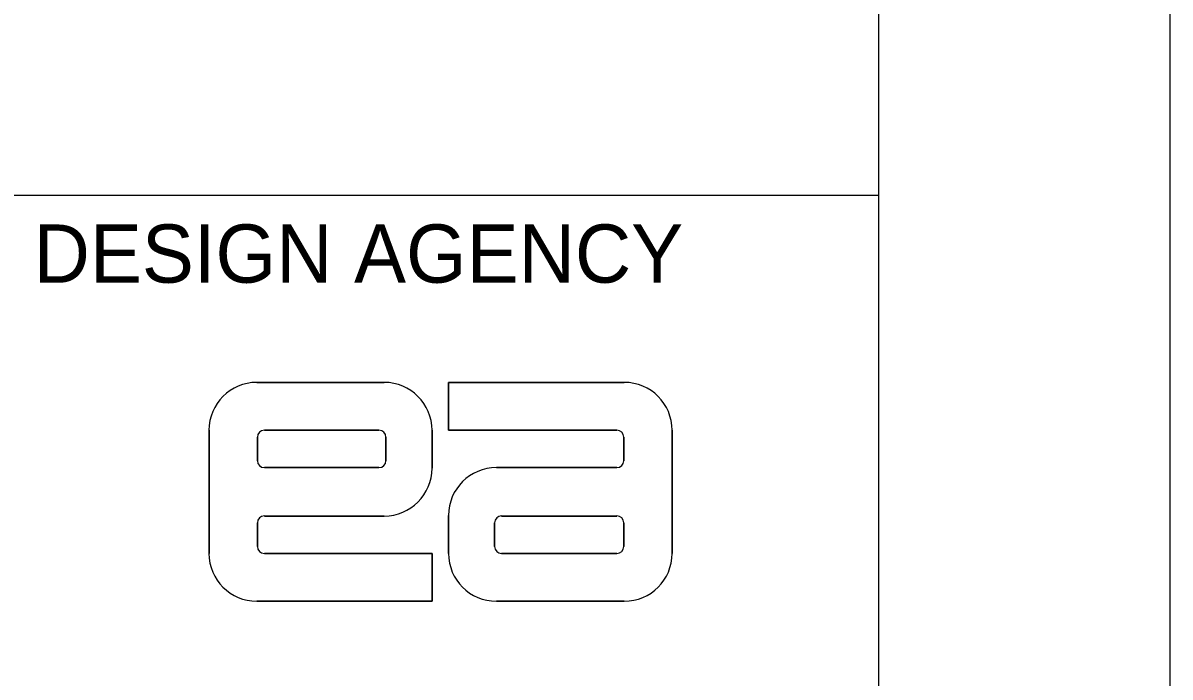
# Model space of a CAD drawing. Extents: x 0 to 34, y 0 to 22.
# Drawn here: x 32.032 to 34, y 3.673 to 4.796 of the extents above; entities that cross this region are included whole.
import ezdxf

# ---------------------------------------------------------------- set-up
doc = ezdxf.new("R2010")
doc.units = 0
for name, color, linetype in [('SH_Border', 7, 'Continuous'), ('SH_Cut_Line', 7, 'Continuous'), ('SH_Data', 7, 'Continuous'), ('TX_X_20', 7, 'Continuous')]:
    doc.layers.add(name, color=color, linetype=linetype)

msp = doc.modelspace()

# ---------------------------------------------------------------- linework, layer by layer
at = {"layer": 'SH_Border'}
msp.add_line((32, 4.5), (33.5, 4.5), dxfattribs=at)
msp.add_lwpolyline([(1.5, 21.5), (33.5, 21.5), (33.5, 0.5), (1.5, 0.5)], close=True, dxfattribs=at)
at = {"layer": 'SH_Cut_Line'}
msp.add_lwpolyline([(0, 0), (34, 0), (34, 22), (0, 22)], close=True, dxfattribs=at)
at = {"layer": 'TX_X_20'}
for p, q in [((32.6515, 4.1788), (32.433, 4.1788)), ((32.433, 4.1788), (32.6515, 4.1788)), ((32.762, 4.1788), (33.0635, 4.1788)), ((32.762, 4.0967), (32.762, 4.1788)), ((32.351, 4.0967), (32.351, 3.8852)), ((32.351, 3.8852), (32.351, 4.0967)), ((32.4459, 4.0967), (32.6426, 4.0967)), ((32.6426, 4.0967), (32.4459, 4.0967)), ((32.7336, 4.0315), (32.7336, 4.0967)), ((32.7336, 4.0967), (32.7336, 4.0315)), ((33.0507, 4.0967), (32.762, 4.0967)), ((33.1456, 3.8852), (33.1456, 4.0967)), ((33.1456, 4.0967), (33.1456, 3.8852)), ((32.434, 4.0444), (32.434, 4.0849)), ((32.434, 4.0849), (32.434, 4.0444)), ((32.6545, 4.0849), (32.6545, 4.0444)), ((32.6545, 4.0444), (32.6545, 4.0849)), ((33.0626, 4.0849), (33.0626, 4.0444)), ((33.0626, 4.0444), (33.0626, 4.0849)), ((32.6426, 4.0325), (32.4459, 4.0325)), ((32.4459, 4.0325), (32.6426, 4.0325)), ((33.0507, 4.0325), (32.8441, 4.0325)), ((32.8441, 4.0325), (33.0507, 4.0325)), ((32.434, 3.8971), (32.434, 3.9376)), ((32.434, 3.9376), (32.434, 3.8971)), ((32.4459, 3.9494), (32.6515, 3.9494)), ((32.6515, 3.9494), (32.4459, 3.9494)), ((32.762, 3.9504), (32.762, 3.8852)), ((32.762, 3.8852), (32.762, 3.9504)), ((32.8411, 3.8971), (32.8411, 3.9376)), ((32.8411, 3.9376), (32.8411, 3.8971)), ((32.853, 3.9494), (33.0507, 3.9494)), ((33.0507, 3.9494), (32.853, 3.9494)), ((33.0626, 3.9376), (33.0626, 3.8971)), ((33.0626, 3.8971), (33.0626, 3.9376)), ((32.4459, 3.8852), (32.7336, 3.8852)), ((32.7336, 3.8852), (32.7336, 3.8031)), ((33.0507, 3.8852), (32.853, 3.8852)), ((32.853, 3.8852), (33.0507, 3.8852)), ((32.7336, 3.8031), (32.433, 3.8031)), ((32.8441, 3.8031), (33.0635, 3.8031)), ((33.0635, 3.8031), (32.8441, 3.8031))]:
    msp.add_line(p, q, dxfattribs=at)
for points in [[(33.0635, 4.1788), (32.762, 4.1788), (32.762, 4.0967), (33.0507, 4.0967)], [(32.433, 3.8031), (32.7336, 3.8031), (32.7336, 3.8852), (32.4459, 3.8852)]]:
    msp.add_lwpolyline(points, dxfattribs=at)
for centre, radius, start, end in [((32.433, 4.0967), 0.0821, 90, 180), ((32.433, 4.0967), 0.0821, 90, 180), ((32.6515, 4.0967), 0.0821, 0, 90), ((32.6515, 4.0967), 0.0821, 0, 90), ((33.0635, 4.0967), 0.0821, 0, 90), ((33.0635, 4.0967), 0.0821, 0, 90), ((32.4459, 4.0849), 0.0119, 90, 180), ((32.4459, 4.0849), 0.0119, 90, 180), ((32.6426, 4.0849), 0.0119, 0, 90), ((32.6426, 4.0849), 0.0119, 0, 90), ((33.0507, 4.0849), 0.0119, 0, 90), ((33.0507, 4.0849), 0.0119, 0, 90), ((32.4459, 4.0444), 0.0119, 180, 270), ((32.4459, 4.0444), 0.0119, 180, 270), ((32.6426, 4.0444), 0.0119, 270, 0), ((32.6426, 4.0444), 0.0119, 270, 0), ((33.0507, 4.0444), 0.0119, 270, 0), ((33.0507, 4.0444), 0.0119, 270, 0), ((32.6515, 4.0315), 0.0821, 270, 360), ((32.6515, 4.0315), 0.0821, 270, 360), ((32.8441, 3.9504), 0.0821, 90, 180), ((32.8441, 3.9504), 0.0821, 90, 180), ((32.4459, 3.9376), 0.0119, 90, 180), ((32.4459, 3.9376), 0.0119, 90, 180), ((32.853, 3.9376), 0.0119, 90, 180), ((32.853, 3.9376), 0.0119, 90, 180), ((33.0507, 3.9376), 0.0119, 0, 90), ((33.0507, 3.9376), 0.0119, 0, 90), ((32.433, 3.8852), 0.0821, 180, 270), ((32.433, 3.8852), 0.0821, 180, 270), ((32.4459, 3.8971), 0.0119, 180, 270), ((32.4459, 3.8971), 0.0119, 180, 270), ((32.8441, 3.8852), 0.0821, 180, 270), ((32.8441, 3.8852), 0.0821, 180, 270), ((32.853, 3.8971), 0.0119, 180, 270), ((32.853, 3.8971), 0.0119, 180, 270), ((33.0507, 3.8971), 0.0119, 270, 0), ((33.0507, 3.8971), 0.0119, 270, 0), ((33.0635, 3.8852), 0.0821, 270, 360), ((33.0635, 3.8852), 0.0821, 270, 360)]:
    msp.add_arc(centre, radius, start, end, dxfattribs=at)

# ---------------------------------------------------------------- texts
at = {"layer": 'SH_Data'}
msp.add_text('DESIGN AGENCY', height=0.1, dxfattribs=at).set_placement((32.05, 4.35))

doc.saveas('drawing.dxf')
